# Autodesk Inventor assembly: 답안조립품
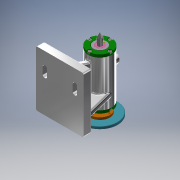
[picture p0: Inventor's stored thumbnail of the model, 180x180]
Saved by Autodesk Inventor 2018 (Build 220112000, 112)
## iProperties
Created: 2022-06
Part Number: 답안조립품
Material: 일반
Document SubType Name: Assembly
Designer: home
Author: home
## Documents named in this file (18)
- C:\Users\kimgi\Desktop\720606V1022\답안조립품.iam
- C:\Users\kimgi\Desktop\720606V1022\본체.ipt
- C:\Users\kimgi\Desktop\720606V1022\나사축.ipt
- C:\Users\kimgi\Desktop\720606V1022\커버.ipt
- C:\Users\kimgi\Desktop\720606V1022\부시.ipt
- C:\Users\kimgi\Desktop\720606V1022\키 4 x 4 x 10.ipt
- C:\Users\kimgi\Desktop\720606V1022\볼트 M3.ipt
- C:\Users\kimgi\Desktop\720606V1022\플랜지.ipt
- C:\Users\kimgi\Desktop\720606V1022\와셔.ipt
- C:\Users\kimgi\Desktop\720606V1022\너트 M8.ipt
- C:\Users\kimgi\Desktop\720606V1022\돌림판.ipt
- C:\Users\kimgi\Desktop\720606V1022\핸들.ipt
- C:\Users\kimgi\Desktop\720606V1022\중공축.ipt
- C:\Users\kimgi\Desktop\720606V1022\슬리브.ipt
- C:\Users\kimgi\Desktop\720606V1022\센터홀더.ipt
- C:\Users\kimgi\Desktop\720606V1022\멈춤나사 M3.ipt
- C:\Users\kimgi\Desktop\720606V1022\센터.ipt
- C:\Users\kimgi\Desktop\720606V1022\나사.ipt
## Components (2 placed, 2 different names)
1. 플랜지:1
2. 핸들:1
